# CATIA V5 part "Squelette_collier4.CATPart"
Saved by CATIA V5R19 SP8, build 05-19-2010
Part number: Squelette_collier4
Bounding box of the stored display mesh (mm): x 200 to 220, y 144 to 200, z 200 to 200
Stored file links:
  G:\EU_thinkMotion\CFAO_2010\MMS_groupe2\MMS_groupe2\A reprendre\jcauchy\Squelette_collier4.CATPart
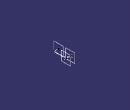
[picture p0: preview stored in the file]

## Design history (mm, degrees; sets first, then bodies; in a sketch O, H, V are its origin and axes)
Parameters
  Longueurcheville_collier4 = 56 mm
  Largueurfixation_collier4 = 20 mm
Set1
  Point1: (200, 200, 200)
  Point2: (220 {= 200mm+Largueurfixation_collier4}, 200, 200)
  Line1: type PtPt, FirstPoint Point2, SecondPoint Point1
  Point3: type OnCurve, Support Line1, RefPoint Point1, Length -20 {= -Largueurfixation_collier4}
  Plane1: type Normal, Curve Line1, RefPoint Point1
  Plane2: type Normal, Curve Line1, RefPoint Point2
  Line2: type Angle, RefPoint Point3, Curve Line1, Support xy-plane, Start 0, End 56 {= Longueurcheville_collier4}, Angle 90
  Line3: type PtDir, RefPoint vertex of Line2, Direction Line1, Start 0, End 20 {= Largueurfixation_collier4}
  Plane3: type Normal, Curve Line3, RefPoint vertex of Line3
Body1 (main body)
